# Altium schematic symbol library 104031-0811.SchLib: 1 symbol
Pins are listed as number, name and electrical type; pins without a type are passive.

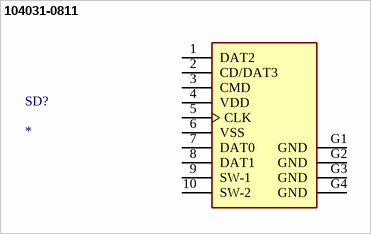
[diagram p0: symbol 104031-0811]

## 104031-0811
designator SD?
Surface Mount Micro SD Card Connector, with Push In Termination ¦ Molex Incorporated 104031-0811
footprint MOLEX_104031-0811
pins: 1 DAT2, 2 CD/DAT3, 3 CMD, 4 VDD, 5 CLK, 6 VSS, 7 DAT0, 8 DAT1, 9 SW-1, 10 SW-2, G1 GND, G2 GND, G3 GND, G4 GND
